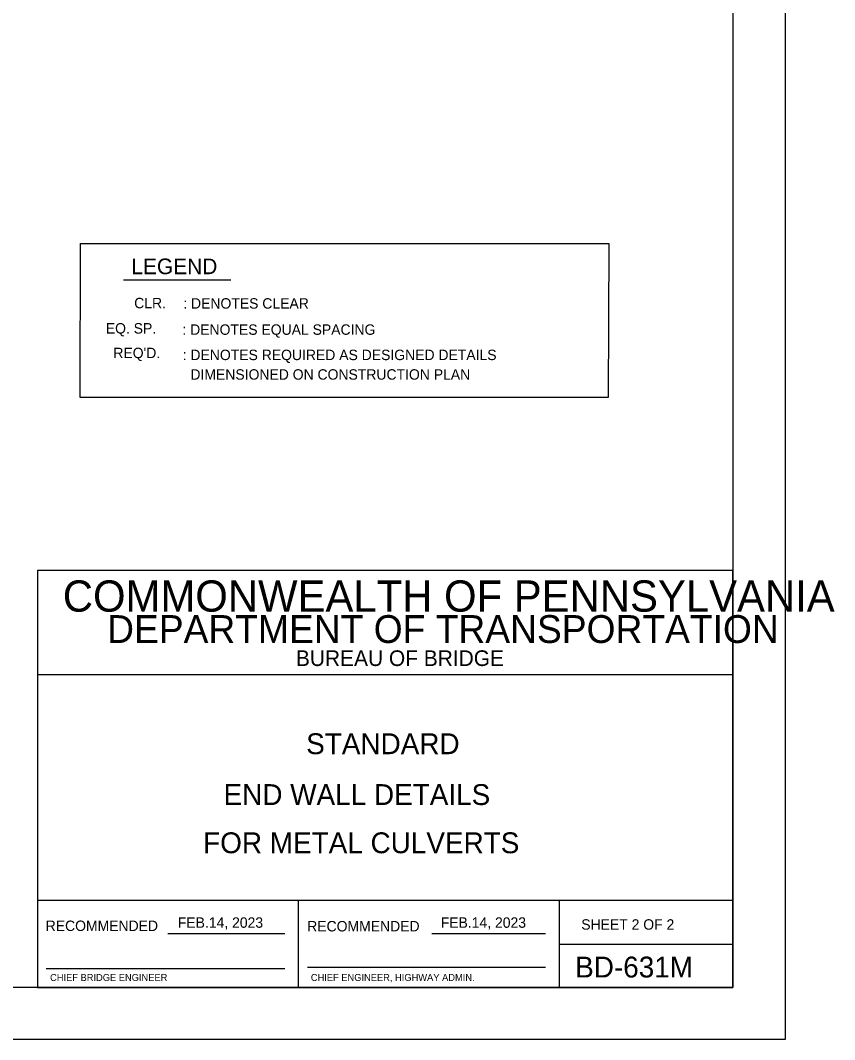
# Model space of a CAD drawing. Extents: x 639011 to 639866, y 298840 to 300028.
# Drawn here: x 639632.3 to 639866.5, y 298839.8 to 299133.1 of the extents above; entities that cross this region are included whole.
import ezdxf

# ---------------------------------------------------------------- set-up
doc = ezdxf.new("R2010")
doc.units = 0
for name, color, linetype in [('2', 7, 'Continuous'), ('DATES', 7, 'Continuous'), ('PLT-BNDY', 7, 'Continuous'), ('SIGNATORY TITLES', 7, 'Continuous')]:
    doc.layers.add(name, color=color, linetype=linetype)

msp = doc.modelspace()

# ---------------------------------------------------------------- linework, layer by layer
at = {"layer": '2'}
for p, q in [((639837.26, 299418.83), (639837.26, 298854.83)), ((639661.97, 299058.43), (639692.84, 299058.43)), ((639837.26, 298974.83), (639637.26, 298974.83)), ((639637.26, 298974.83), (639637.26, 298854.83)), ((639837.26, 298854.83), (639837.26, 298974.83)), ((639837.26, 298944.83), (639637.26, 298944.83)), ((639837.26, 298879.83), (639637.26, 298879.83)), ((639712.26, 298854.83), (639712.26, 298879.83)), ((639787.26, 298879.83), (639787.26, 298854.83)), ((639674.71, 298870.33), (639708.4, 298870.33)), ((639750.69, 298870.33), (639783.31, 298870.33)), ((639787.26, 298867.33), (639837.26, 298867.33)), ((639639.76, 298860.33), (639708.4, 298860.33)), ((639714.88, 298860.71), (639783.31, 298860.71)), ((639837.26, 298854.83), (639051.26, 298854.83)), ((639637.26, 298854.83), (639837.26, 298854.83))]:
    msp.add_line(p, q, dxfattribs=at)
msp.add_lwpolyline([(639801.52, 299068.85), (639801.41, 299024.59), (639649.53, 299024.59), (639649.64, 299068.85)], close=True, dxfattribs=at)
at = {"layer": 'PLT-BNDY'}
msp.add_lwpolyline([(639011.26, 299433.83), (639852.26, 299433.83), (639852.26, 298839.83), (639011.26, 298839.83)], close=True, dxfattribs=at)

# ---------------------------------------------------------------- texts
at = {"layer": '2'}
for s, height, p in [('LEGEND', 4.5, (639664.22, 299060.06)), ('CLR.', 3, (639665.05, 299050.25)), (': DENOTES CLEAR', 3, (639679.16, 299050.15)), ('EQ. SP.', 3, (639656.88, 299042.98)), (': DENOTES EQUAL SPACING', 3, (639678.91, 299042.62)), ("REQ'D.", 3, (639659.05, 299035.9)), (': DENOTES REQUIRED AS DESIGNED DETAILS', 3, (639678.99, 299035.34)), ('  DIMENSIONED ON CONSTRUCTION PLAN', 3, (639678.99, 299029.71)), ('COMMONWEALTH OF PENNSYLVANIA', 9, (639644.51, 298962.96)), ('DEPARTMENT OF TRANSPORTATION', 8.0002, (639657.26, 298953.96)), ('BUREAU OF BRIDGE', 4.5, (639711.56, 298947.33)), ('STANDARD', 6, (639714.51, 298921.96)), ('END WALL DETAILS', 6, (639690.76, 298907.33)), ('FOR METAL CULVERTS', 6, (639684.88, 298893.46)), ('SHEET 2 OF 2', 3, (639793.63, 298871.46)), ('BD-631M', 6, (639791.88, 298857.71))]:
    msp.add_text(s, height=height, dxfattribs=at).set_placement(p)
for p in [(639639.59, 298871.08), (639714.81, 298870.96)]:
    msp.add_text('RECOMMENDED', height=3, rotation=360, dxfattribs=at).set_placement(p)
at = {"layer": 'DATES'}
for p in [(639677.59, 298872.01), (639753.21, 298872.01)]:
    msp.add_text('FEB.14, 2023', height=3, dxfattribs=at).set_placement(p)
at = {"layer": 'SIGNATORY TITLES'}
for s, p in [('CHIEF BRIDGE ENGINEER', (639640.85, 298856.71)), ('CHIEF ENGINEER, HIGHWAY ADMIN.', (639715.85, 298856.71))]:
    msp.add_text(s, height=2, dxfattribs=at).set_placement(p)

doc.saveas('drawing.dxf')
